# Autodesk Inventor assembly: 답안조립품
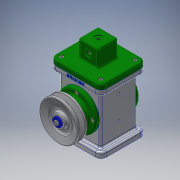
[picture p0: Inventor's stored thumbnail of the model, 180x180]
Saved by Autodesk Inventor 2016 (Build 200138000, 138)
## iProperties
Created: 2017-08
Part Number: 답안조립품
Material: 일반
Document SubType Name: Assembly
Designer: USER
Author: USER
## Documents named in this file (18)
- C:\Users\USER\Desktop\470808V1017\답안조립품.iam
- C:\Users\USER\Desktop\470808V1017\E-링.ipt
- C:\Users\USER\Desktop\470808V1017\V-벨트풀리.ipt
- C:\Users\USER\Desktop\470808V1017\덮개.ipt
- C:\Users\USER\Desktop\470808V1017\뒤커버.ipt
- C:\Users\USER\Desktop\470808V1017\링크.ipt
- C:\Users\USER\Desktop\470808V1017\베어링 17 x 40 x 12.ipt
- C:\Users\USER\Desktop\470808V1017\본체.ipt
- C:\Users\USER\Desktop\470808V1017\볼트 M4 x 8.ipt
- C:\Users\USER\Desktop\470808V1017\볼트 M4 x 10.ipt
- C:\Users\USER\Desktop\470808V1017\슬라이더.ipt
- C:\Users\USER\Desktop\470808V1017\앞커버.ipt
- C:\Users\USER\Desktop\470808V1017\오일 실 17 30 8.ipt
- C:\Users\USER\Desktop\470808V1017\와셔 4x16.ipt
- C:\Users\USER\Desktop\470808V1017\클레비스 핀 6 x 22.ipt
- 클레비스 핀 6 x 22.ipt
- C:\Users\USER\Desktop\470808V1017\키 4 x 4 x 12.ipt
- C:\Users\USER\Desktop\470808V1017\편심축.ipt
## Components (2 placed, 2 different names)
1. E-링:1
2. V-벨트풀리:1
